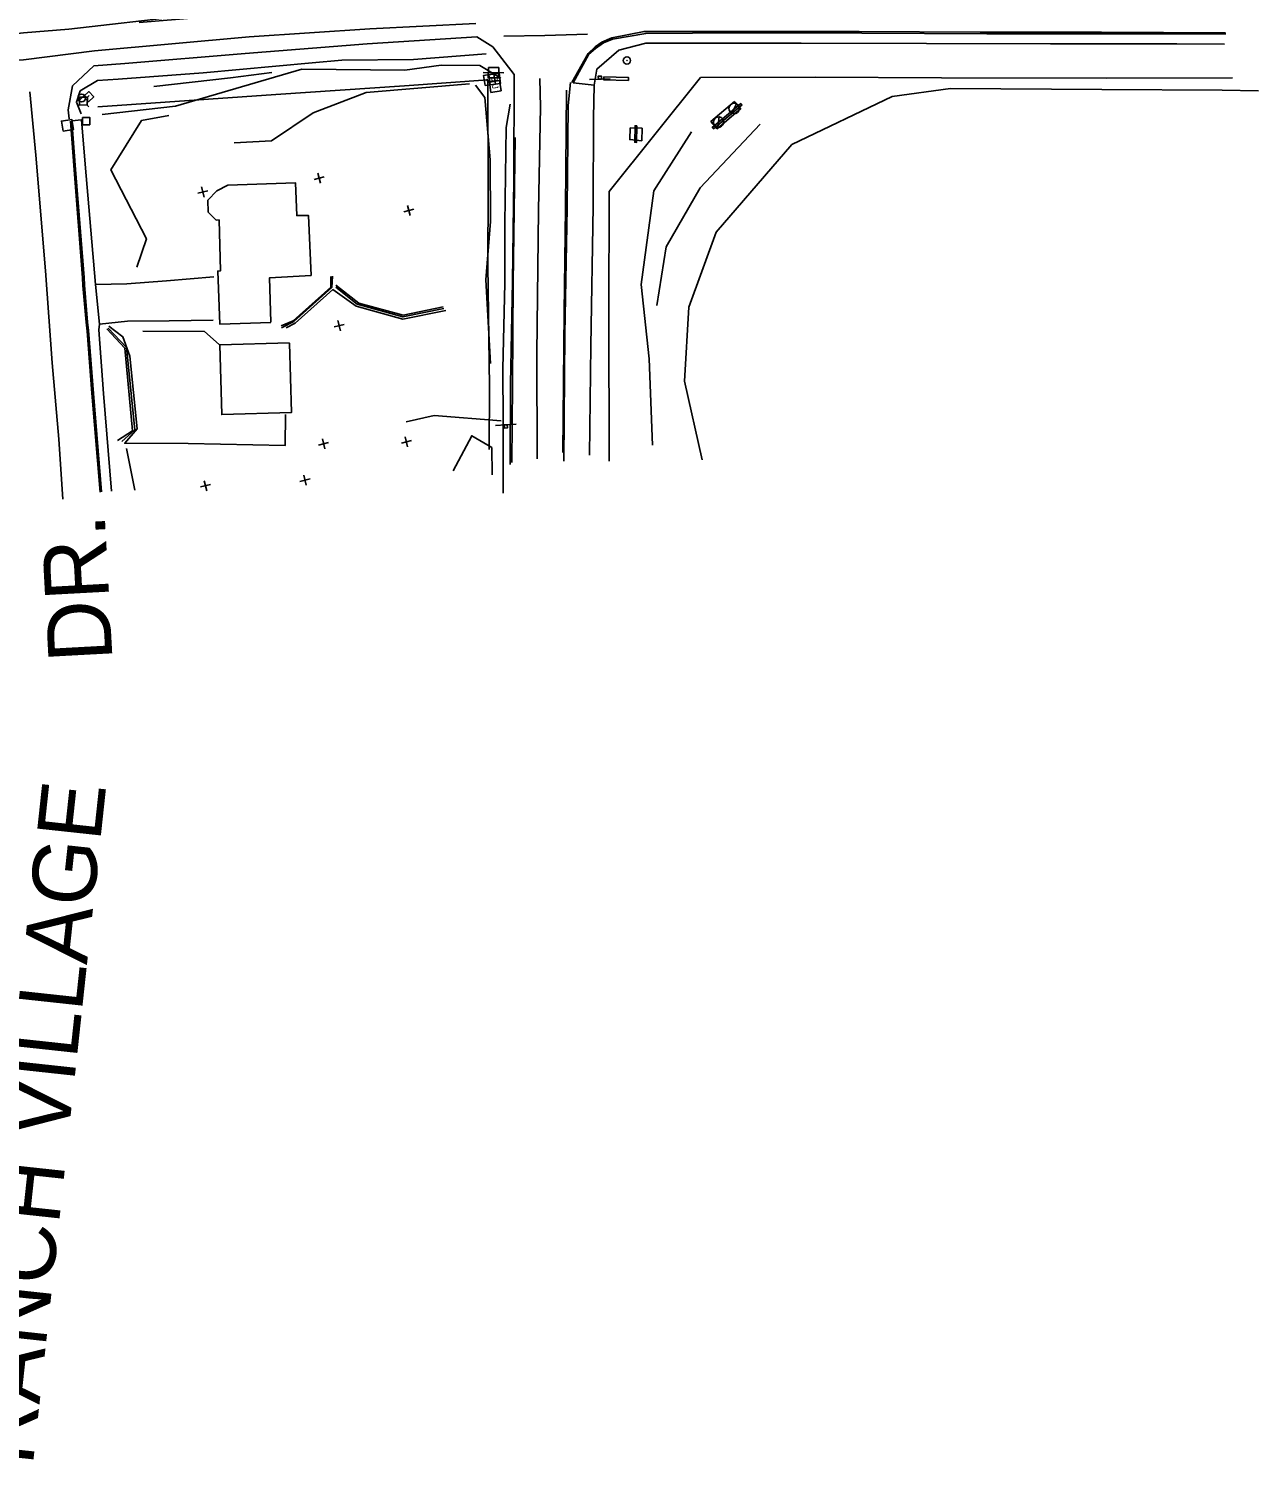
# Model space of a CAD drawing. Extents: x 4711259 to 4716401, y 890074 to 892728.
# Drawn here: x 4715789 to 4716382, y 890547 to 891237 of the extents above; entities that cross this region are included whole.
import ezdxf

# ---------------------------------------------------------------- set-up
doc = ezdxf.new("R2010")
doc.units = 0
for name, color, linetype in [('E_GT_WALL_Retaining', 7, 'Continuous'), ('E_HY_STORM_Inlet', 7, 'Continuous'), ('E_RDWY_PHOTOG_Eave', 7, 'Continuous'), ('E_RDWY_PHOTOG_Fence', 7, 'Continuous'), ('E_RDWY_ROAD_Approach', 7, 'Continuous'), ('E_RDWY_ROAD_Bikeway', 7, 'Continuous'), ('E_RDWY_ROAD_Curb', 7, 'Continuous'), ('E_RDWY_ROAD_EdgeAsph', 7, 'Continuous'), ('E_RDWY_ROAD_EdgeConc', 7, 'Continuous'), ('E_RDWY_ROAD_EdgeGravel', 7, 'Continuous'), ('E_RDWY_ROAD_Fence', 7, 'Continuous'), ('E_RDWY_ROAD_NameTx', 7, 'Continuous'), ('E_RDWY_ROAD_Sidewalk', 7, 'Continuous'), ('E_RDWY_ROAD_Striping', 7, 'Continuous'), ('E_RDWY_ROAD_TBofCurb', 7, 'Continuous'), ('E_TERR_DTM_BrkLines', 7, 'Continuous'), ('E_TERR_DTM_RandomPt', 7, 'Continuous'), ('E_TRAF_PHOTOG_Signs', 7, 'Continuous'), ('E_TRAF_SIGN_PrivateSign', 7, 'Continuous'), ('E_TRAF_SIGN_PublicSign', 7, 'Continuous'), ('E_UTIL_COMM_General', 7, 'Continuous'), ('E_UTIL_ELEC_POLE', 7, 'Continuous'), ('E_UTIL_MISC_General', 7, 'Continuous'), ('E_UTIL_WTR_General', 7, 'Continuous')]:
    doc.layers.add(name, color=color, linetype=linetype)

msp = doc.modelspace()

# ---------------------------------------------------------------- linework, layer by layer
at = {"layer": 'E_GT_WALL_Retaining'}
for points in [[(4715935.84, 891117.61), (4715935.41, 891112.05), (4715917.14, 891095.74), (4715911.19, 891092.61)], [(4715937.39, 891112.26), (4715947.75, 891104.03), (4715969.75, 891097.96), (4715989.55, 891102.01)], [(4715834.27, 891037.89), (4715840.54, 891043.58), (4715836.44, 891083.19), (4715827.63, 891092.47)]]:
    msp.add_lwpolyline(points, dxfattribs=at)
at = {"layer": 'E_HY_STORM_Inlet'}
msp.add_line((4715807.98, 891190.28), (4715807.98, 891190.28), dxfattribs=at)
msp.add_lwpolyline([(4715805.92, 891187.41), (4715805.1, 891192.34), (4715810.04, 891193.15), (4715810.85, 891188.22)], close=True, dxfattribs=at)
at = {"layer": 'E_RDWY_PHOTOG_Eave'}
for points in [[(4715906.08, 891095.33), (4715881.41, 891094.52), (4715880.44, 891120.04), (4715881.86, 891120.19), (4715881.13, 891144.72), (4715879.66, 891144.65), (4715875.8, 891148.49), (4715875.75, 891154.24), (4715880.03, 891158.68), (4715885.36, 891161.53), (4715917.9, 891162.64), (4715918.57, 891146.79), (4715924.3, 891146.76), (4715925.44, 891117.95), (4715905.4, 891116.75), (4715906.08, 891095.37)], [(4715915.06, 891085.43), (4715881.47, 891084.51), (4715882.36, 891050.9), (4715915.96, 891051.84), (4715915.04, 891085.34)]]:
    msp.add_lwpolyline(points, dxfattribs=at)
at = {"layer": 'E_RDWY_PHOTOG_Fence'}
for points in [[(4716011.35, 891033.97), (4716011.48, 891064.29), (4716010.79, 891122.88), (4716010.81, 891159.68), (4716010.75, 891212.22), (4715970.48, 891209.34), (4715908.44, 891205.12), (4715822.69, 891199.14)], [(4716113.23, 891213.36), (4716168.63, 891213.54), (4716229.49, 891213.19), (4716309.27, 891213.09), (4716369.75, 891213.19)]]:
    msp.add_lwpolyline(points, dxfattribs=at)
at = {"layer": 'E_RDWY_ROAD_Approach'}
for points in [[(4715821.57, 891113.63), (4715836.6, 891113.87), (4715855.83, 891115.35), (4715878.61, 891117.29)], [(4715878.29, 891096.3), (4715856.97, 891096), (4715836.99, 891095.92), (4715823.52, 891094.46)]]:
    msp.add_lwpolyline(points, dxfattribs=at)
at = {"layer": 'E_RDWY_ROAD_Bikeway'}
for points in [[(4716047.33, 891028.36), (4716047.92, 891089.83), (4716049.03, 891150.38), (4716049.42, 891199.88), (4716050.59, 891210.94)], [(4716059.67, 891031.37), (4716060.37, 891083.93), (4716061.54, 891151.25), (4716061.72, 891193.94), (4716062.06, 891209.66)]]:
    msp.add_lwpolyline(points, dxfattribs=at)
at = {"layer": 'E_RDWY_ROAD_Curb'}
for points in [[(4716051.17, 891210.94), (4716059.08, 891224.98), (4716062.4, 891228.16), (4716065.75, 891230.36), (4716070.46, 891232.47), (4716086.03, 891235.54), (4716132.17, 891235.56), (4716189.82, 891235.47), (4716248.08, 891235.25), (4716306.67, 891235.2), (4716366.4, 891234.95)], [(4715823.76, 891013.48), (4715819.8, 891061.22), (4715817.45, 891091.06), (4715817.04, 891095.41), (4715815.44, 891113.1), (4715815.29, 891116.83), (4715811.16, 891168.89), (4715809.48, 891192.28)]]:
    msp.add_lwpolyline(points, dxfattribs=at)
at = {"layer": 'E_RDWY_ROAD_EdgeAsph'}
for points in [[(4716005.35, 891233.01), (4715952.5, 891229.56), (4715893.76, 891224.89), (4715835.7, 891220.17), (4715820.7, 891218.97), (4715810.37, 891209.28), (4715808.37, 891197.71), (4715808.81, 891193.48)], [(4716005.35, 891233.01), (4716013.12, 891228.13), (4716023.48, 891214.74), (4716023.29, 891164.41), (4716022.61, 891114.97), (4716021.6, 891065.73), (4716021.43, 891026.86)]]:
    msp.add_lwpolyline(points, dxfattribs=at)
at = {"layer": 'E_RDWY_ROAD_EdgeConc'}
msp.add_lwpolyline([(4716129.7, 891201.86), (4716118.33, 891192.11), (4716121.33, 891188.61), (4716132.71, 891198.35)], close=True, dxfattribs=at)
for points in [[(4716085.04, 891182.76), (4716079.14, 891183.44), (4716079.32, 891189.16)], [(4716079.32, 891189.16), (4716085.12, 891188.88), (4716085.04, 891182.76)]]:
    msp.add_lwpolyline(points, dxfattribs=at)
at = {"layer": 'E_RDWY_ROAD_EdgeGravel'}
for points in [[(4716009.92, 891224.72), (4715974.94, 891222.07), (4715940.31, 891221.63), (4715925.92, 891220.4), (4715873.45, 891215.64), (4715832.49, 891212.55), (4715822.47, 891211.89), (4715814.06, 891206.89), (4715812.28, 891201.47), (4715814.6, 891195.77)], [(4715913.08, 891050.91), (4715913.04, 891036.03), (4715866.18, 891036.87), (4715835.58, 891037.05), (4715841.53, 891044.05), (4715838.04, 891078.96), (4715834.75, 891088.42), (4715827.9, 891093.45)]]:
    msp.add_lwpolyline(points, dxfattribs=at)
at = {"layer": 'E_RDWY_ROAD_Fence'}
msp.add_lwpolyline([(4716113.23, 891213.36), (4716069.18, 891158.33), (4716069.12, 891098.98), (4716069.22, 891028.44)], dxfattribs=at)
at = {"layer": 'E_RDWY_ROAD_Sidewalk'}
for points in [[(4716051.82, 891210.79), (4716062.06, 891209.66), (4716063.33, 891217.4), (4716073.85, 891226.57), (4716086.87, 891229.92), (4716161.75, 891229.94), (4716222.2, 891229.75), (4716282.11, 891229.63), (4716343, 891229.65), (4716365.94, 891229.49)], [(4715829.28, 891013.98), (4715825.45, 891061.1), (4715823.04, 891091.75), (4715823.52, 891094.46), (4715821.57, 891113.63), (4715816.47, 891171.57), (4715814.8, 891193.02), (4715810.1, 891192.53)]]:
    msp.add_lwpolyline(points, dxfattribs=at)
at = {"layer": 'E_RDWY_ROAD_Striping'}
for points in [[(4715808.61, 891236.7), (4715864.76, 891243.12), (4715913.52, 891249.89), (4715967.93, 891251.36), (4715996.78, 891249.87), (4715944.11, 891247.6), (4715898.87, 891244.46), (4715842.49, 891239.81)], [(4715820.97, 891226.18), (4715895.6, 891232.92), (4715953.86, 891236.78), (4716004.85, 891239.39)], [(4716046.89, 891032.67), (4716047.53, 891100.19), (4716048.14, 891150.17), (4716048.68, 891207.26)], [(4716023.92, 891184.44), (4716023.36, 891149.11)], [(4716023.36, 891149.11), (4716022.88, 891114.52), (4716022.54, 891065.08), (4716022.33, 891027.82)]]:
    msp.add_lwpolyline(points, dxfattribs=at)
at = {"layer": 'E_RDWY_ROAD_TBofCurb'}
for points in [[(4716366.68, 891234.33), (4716306.39, 891234.39), (4716251.37, 891234.42), (4716191.14, 891234.68), (4716131.84, 891234.86), (4716086.83, 891234.6), (4716070.84, 891231.87), (4716066.48, 891230.03), (4716062.58, 891227.37), (4716059.42, 891224.56), (4716051.82, 891210.79)], [(4715810.1, 891192.53), (4715811.83, 891169.06), (4715815.99, 891116.91), (4715816.16, 891113.24), (4715817.66, 891095.37), (4715818.15, 891091.35), (4715820.62, 891061.1), (4715824.42, 891013.71)]]:
    msp.add_lwpolyline(points, dxfattribs=at)
at = {"layer": 'E_TERR_DTM_BrkLines'}
for points in [[(4715753.79, 891231.19), (4715786.85, 891234.87), (4715808.61, 891236.7)], [(4716018.42, 891233.27), (4716038.16, 891233.63), (4716058.74, 891234.32)], [(4715820.97, 891226.18), (4715786.72, 891221.93), (4715753.16, 891220.13)], [(4715824.74, 891195.57), (4715860.17, 891199.61), (4715921.01, 891217.42), (4715970.74, 891216.85), (4715988.15, 891219.22), (4716006.9, 891219.19), (4716016.92, 891212.99)], [(4715906.5, 891215.77), (4715886.54, 891213.12), (4715849.65, 891209.08)], [(4716001.85, 891210.25), (4715952.01, 891206.19), (4715926.5, 891196.39), (4715906.44, 891182.77), (4715888.45, 891181.86)], [(4716004.77, 891209.64), (4716009.25, 891203.74), (4716011.77, 891173.72), (4716011.98, 891143.98), (4716009.75, 891115.89), (4716012.04, 891075.55)], [(4716034.52, 891029.5), (4716034.36, 891080.23), (4716035.12, 891149.46), (4716036.13, 891199.02), (4716035.77, 891212.84)], [(4715789.87, 891206.39), (4715792.72, 891175.92), (4715797.35, 891120.22), (4715800.59, 891075.82), (4715803.88, 891038.94), (4715805.7, 891010.05)], [(4716114, 891029.07), (4716105.51, 891066.92), (4716107.63, 891102.59), (4716120.89, 891138.74), (4716157.34, 891181.1), (4716205.77, 891204.16), (4716233.77, 891207.98), (4716306.87, 891207.61), (4716364.83, 891207.18), (4716382.31, 891206.86)], [(4716021.47, 891200.42), (4716019.5, 891189.32), (4716018.96, 891142.98), (4716018.86, 891114.28), (4716017.91, 891072.84), (4716018.06, 891047.69), (4716018.04, 891013.04)], [(4715841.41, 891121.89), (4715846.06, 891135.61), (4715828.87, 891168.77), (4715843.76, 891192.64), (4715856.82, 891195.1)], [(4716142.07, 891190.8), (4716113.17, 891160.21), (4716096.77, 891131.74), (4716092.2, 891103.38)], [(4716090.13, 891036.16), (4716088.58, 891077.69), (4716084.67, 891113.56), (4716090.72, 891158.71), (4716108.87, 891187.12)], [(4715935.03, 891117.43), (4715935.05, 891112.23), (4715916.82, 891096.12), (4715911.01, 891093.68)], [(4715989.23, 891102.81), (4715969.91, 891098.86), (4715948.56, 891104.55), (4715937.41, 891113.32)], [(4715913.46, 891092.62), (4715917.74, 891094.93), (4715935.94, 891111.16), (4715947.27, 891103.18), (4715969.67, 891096.92), (4715990.46, 891101.03)], [(4715826.95, 891092.26), (4715835.7, 891082.89), (4715839.4, 891042.99), (4715832.18, 891038.43)], [(4715881.09, 891084.67), (4715874.03, 891090.87), (4715844.32, 891091.01)], [(4716017.19, 891047.9), (4715984.82, 891050.38), (4715971.37, 891047.44)], [(4716012.76, 891021.81), (4716012.65, 891034.93), (4716002.97, 891040.64), (4715994.07, 891023.68)], [(4715836.41, 891034.56), (4715840.51, 891014.47)]]:
    msp.add_lwpolyline(points, dxfattribs=at)
at = {"layer": 'E_TERR_DTM_RandomPt'}
for p, q in [((4715931.83, 891165.48), (4715926.99, 891164.25)), ((4715928.79, 891167.29), (4715930.02, 891162.44)), ((4715875.71, 891158.76), (4715870.87, 891157.53)), ((4715872.67, 891160.57), (4715873.91, 891155.72)), ((4715975.03, 891149.85), (4715970.18, 891148.62)), ((4715971.99, 891151.66), (4715973.22, 891146.82)), ((4715941.43, 891094.33), (4715936.58, 891093.1)), ((4715938.39, 891096.14), (4715939.62, 891091.29)), ((4715933.94, 891037.36), (4715929.1, 891036.13)), ((4715930.91, 891039.17), (4715932.14, 891034.32)), ((4715973.85, 891038.39), (4715969, 891037.16)), ((4715970.81, 891040.2), (4715972.04, 891035.36)), ((4715876.94, 891017.21), (4715872.09, 891015.97)), ((4715873.9, 891019.01), (4715875.13, 891014.17)), ((4715924.96, 891019.85), (4715920.12, 891018.62)), ((4715921.92, 891021.66), (4715923.15, 891016.81))]:
    msp.add_line(p, q, dxfattribs=at)
at = {"layer": 'E_TRAF_PHOTOG_Signs'}
for points in [[(4716133.31, 891200.11), (4716119.48, 891188.65), (4716118.94, 891189.31), (4716132.76, 891200.77)], [(4716082.62, 891190.04), (4716082.44, 891182.1), (4716081.57, 891182.12), (4716081.75, 891190.06)]]:
    msp.add_lwpolyline(points, close=True, dxfattribs=at)
at = {"layer": 'E_TRAF_SIGN_PrivateSign'}
msp.add_lwpolyline([(4716066.59, 891213.62), (4716078.5, 891213.38), (4716078.47, 891211.98), (4716066.56, 891212.23)], close=True, dxfattribs=at)
at = {"layer": 'E_TRAF_SIGN_PublicSign'}
for p, q in [((4716069.76, 891212.67), (4716059.76, 891212.39)), ((4716064.74, 891213.28), (4716064.74, 891213.28)), ((4716014.35, 891045.57), (4716024.33, 891046.23)), ((4716019.39, 891045.15), (4716019.39, 891045.15))]:
    msp.add_line(p, q, dxfattribs=at)
for points in [[(4716065.51, 891212.55), (4716065.47, 891214.05), (4716063.97, 891214.01), (4716064.01, 891212.51)], [(4716018.59, 891045.85), (4716018.69, 891044.36), (4716020.18, 891044.46), (4716020.09, 891045.95)]]:
    msp.add_lwpolyline(points, close=True, dxfattribs=at)
at = {"layer": 'E_UTIL_COMM_General'}
for points in [[(4716009.41, 891209.43), (4716008.67, 891214.38), (4716013.61, 891215.12), (4716014.36, 891210.18)], [(4716011.89, 891209.76), (4716011.15, 891214.71), (4716016.1, 891215.45), (4716016.84, 891210.51)], [(4716012.19, 891206.2), (4716011.44, 891211.14), (4716016.39, 891211.89), (4716017.13, 891206.94)], [(4715815.71, 891204.24), (4715818.3, 891206.59), (4715820.65, 891204), (4715818.06, 891201.65)], [(4715815.32, 891194.08), (4715818.82, 891194.04), (4715818.77, 891190.54), (4715815.27, 891190.58)]]:
    msp.add_lwpolyline(points, close=True, dxfattribs=at)
at = {"layer": 'E_UTIL_ELEC_POLE'}
msp.add_line((4716008.42, 891215.74), (4716018.42, 891215.61), dxfattribs=at)
msp.add_lwpolyline([(4716010.96, 891218.21), (4716015.96, 891218.14), (4716015.89, 891213.14), (4716010.89, 891213.21)], close=True, dxfattribs=at)
at = {"layer": 'E_UTIL_MISC_General'}
for p, q in [((4716077.9, 891221.44), (4716077.68, 891221.65)), ((4716077.68, 891221.43), (4716077.89, 891221.65)), ((4716128.35, 891196.19), (4716130.58, 891200.66)), ((4716122.3, 891194.35), (4716121.6, 891189.4))]:
    msp.add_line(p, q, dxfattribs=at)
msp.add_circle((4716077.79, 891221.57), 1.75, dxfattribs=at)
for centre, start, end in [((4716129.47, 891198.42), 63.58003, 243.58003), ((4716129.47, 891198.42), 243.58003, 63.58003), ((4716121.95, 891191.87), 81.99404, 261.99404), ((4716121.95, 891191.87), 261.99404, 81.99404)]:
    msp.add_arc(centre, 2.5, start, end, dxfattribs=at)
at = {"layer": 'E_UTIL_WTR_General'}
for p, q in [((4715813.83, 891203.87), (4715813.01, 891204.72)), ((4715816.17, 891204.78), (4715813.49, 891202.16)), ((4715817.58, 891203.82), (4715818.43, 891204.65)), ((4715813.79, 891200.12), (4715812.94, 891199.3)), ((4715817.54, 891200.07), (4715818.36, 891199.23))]:
    msp.add_line(p, q, dxfattribs=at)
msp.add_lwpolyline([(4715813.79, 891200.12), (4715813.83, 891203.87), (4715817.58, 891203.82), (4715817.54, 891200.07)], close=True, dxfattribs=at)
msp.add_circle((4715814.83, 891203.47), 1.87, dxfattribs=at)

# ---------------------------------------------------------------- texts
at = {"layer": 'E_RDWY_ROAD_NameTx'}
for s, height, rotation, p in [('DR.', 30.84, 93.09958, (4715829.76, 890932.41)), ('RANCH VILLAGE', 30.8399, 83.83149, (4715791.25, 890543.87))]:
    msp.add_text(s, height=height, rotation=rotation, dxfattribs=at).set_placement(p)
at = {"layer": 'E_UTIL_COMM_General'}
for p in [(4716009.83, 891212.88), (4716012.32, 891213.21), (4716012.61, 891209.65)]:
    msp.add_text('J', height=3, rotation=278.55016, dxfattribs=at).set_placement(p)

doc.saveas('drawing.dxf')
